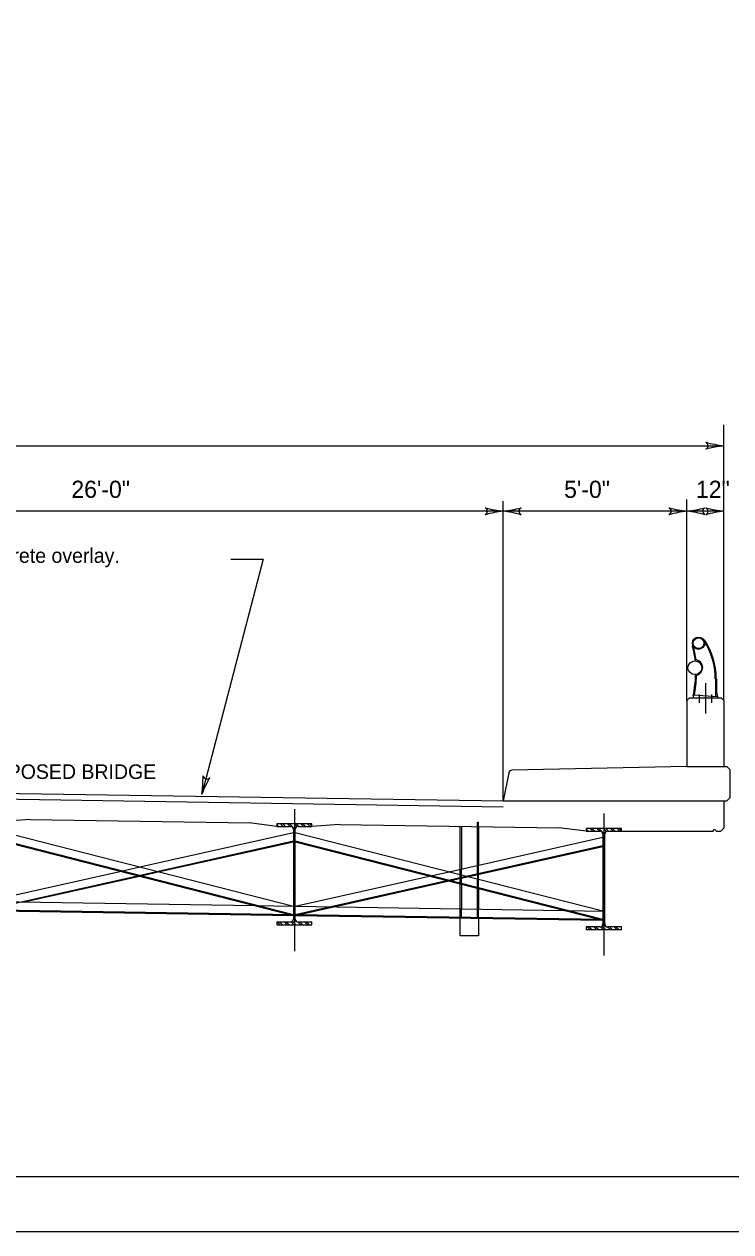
# Model space of a CAD drawing. Extents: x -706 to 14950, y -1867 to 6417.
# Drawn here: x -41.4 to 150.8, y -336.5 to -7.9 of the extents above; entities that cross this region are included whole.
import ezdxf

# ---------------------------------------------------------------- set-up
doc = ezdxf.new("R2010")
doc.units = 0
for name, color, linetype in [('Level 1', 7, 'Continuous'), ('Level 42', 7, 'Continuous'), ('Level 43', 7, 'Continuous'), ('Level 44', 7, 'Continuous'), ('Level 47', 7, 'Continuous'), ('Level 48', 7, 'Continuous')]:
    doc.layers.add(name, color=color, linetype=linetype)

msp = doc.modelspace()

# ---------------------------------------------------------------- linework, layer by layer
at = {"layer": 'Level 1'}
for p, q in [((143.95, -121.66), (143.94, -121.66)), ((93.71, -139.49), (93.72, -139.49)), ((143.71, -139.49), (143.72, -139.49)), ((83.95, -141.34), (83.94, -141.34)), ((133.95, -141.34), (133.94, -141.34)), ((143.95, -141.34), (143.94, -141.34))]:
    msp.add_line(p, q, dxfattribs=at)
for points in [[(-574.95, 323.53), (445.05, 323.53), (445.05, -336.47), (-574.95, -336.47)], [(-514.95, 308.53), (430.05, 308.53), (430.05, -321.47), (-514.95, -321.47)]]:
    msp.add_lwpolyline(points, close=True, dxfattribs=at)
for centre, start, end in [((153.23, -86.04), 255.3829, 263.1374), ((153.23, -159.12), 96.8626, 104.6171), ((93.23, -103.87), 255.3829, 263.1374), ((93.23, -176.95), 96.8626, 104.6171), ((84.43, -103.87), 276.8626, 284.6171), ((84.43, -176.95), 75.3829, 83.1374), ((143.23, -103.87), 255.3829, 263.1374), ((143.23, -176.95), 96.8626, 104.6171), ((134.43, -103.87), 276.8626, 284.6171), ((134.43, -176.95), 75.3829, 83.1374), ((153.23, -103.87), 255.3829, 263.1374), ((153.23, -176.95), 96.8626, 104.6171)]:
    msp.add_arc(centre, 36.8, start, end, dxfattribs=at)
for centre, major_axis, start_param, end_param in [((143.29, -122.58), (1.25, 0), 5.258637, 7.300638), ((83.29, -140.42), (1.25, 0), 5.265733, 7.307734), ((94.37, -140.41), (-1.25, 0), 5.265733, 7.307734), ((133.29, -140.42), (1.25, 0), 5.265733, 7.307734), ((144.37, -140.41), (-1.25, 0), 5.265733, 7.307734), ((143.29, -140.42), (1.25, 0), 5.265733, 7.307734)]:
    msp.add_ellipse(centre, major_axis=major_axis, ratio=0.873734, start_param=start_param, end_param=end_param, dxfattribs=at)
at = {"layer": 'Level 42'}
for p, q in [((143.83, -187.2), (143.83, -195.43)), ((142.16, -190.23), (142.16, -192.5)), ((145.5, -190.23), (145.5, -192.56)), ((138.83, -209.85), (148.83, -209.85)), ((-136.27, -215.71), (88.83, -219.22)), ((-136.27, -217.3), (88.83, -220.81))]:
    msp.add_line(p, q, dxfattribs=at)
at = {"layer": 'Level 43'}
for p, q in [((140.31, -177.1), (140.5, -177.05)), ((143.4, -175.45), (143.58, -175.35)), ((146.55, -185.98), (146.55, -190.85)), ((146.82, -186.01), (146.82, -189.18)), ((140.52, -190.49), (140.52, -191.31)), ((147.15, -190.89), (140.52, -190.49)), ((138.83, -191.94), (139.45, -191.31)), ((138.83, -191.94), (138.83, -209.85)), ((148.21, -191.31), (139.45, -191.31)), ((147.15, -190.89), (147.15, -191.31)), ((148.83, -191.94), (148.21, -191.31)), ((148.83, -191.94), (148.83, -209.85)), ((138.83, -209.85), (91.17, -210.88)), ((148.83, -209.85), (149.66, -209.85)), ((149.66, -209.85), (150.5, -210.68)), ((90.37, -211.55), (88.83, -219.23)), ((150.5, -210.68), (150.5, -218.39)), ((88.83, -219.23), (148.83, -219.23)), ((148.83, -219.23), (149.66, -219.23)), ((148.83, -219.23), (148.83, -226.63)), ((150.5, -218.39), (149.66, -219.23)), ((-51.86, -226.5), (31.82, -247.86)), ((-39.81, -224.3), (-47.31, -224.84)), ((-39.81, -224.3), (20.08, -225.23)), ((27.27, -226.15), (19.77, -225.23)), ((36.85, -225.42), (27.27, -225.42)), ((27.27, -225.42), (27.27, -226.15)), ((27.77, -226.15), (27.27, -225.65)), ((27.27, -226.15), (30.99, -226.15)), ((29.04, -226.15), (28.31, -225.42)), ((29.61, -226.15), (28.88, -225.42)), ((30.88, -226.15), (30.15, -225.42)), ((32.3, -227.01), (30.72, -225.42)), ((32.81, -226.24), (31.99, -225.42)), ((33.29, -226.15), (32.56, -225.42)), ((33.14, -226.15), (36.85, -226.15)), ((33.14, -226.15), (33.14, -226.15)), ((34.56, -226.15), (33.83, -225.42)), ((35.12, -226.15), (34.4, -225.42)), ((36.4, -226.15), (35.67, -225.42)), ((36.85, -226.04), (36.23, -225.42)), ((36.85, -226.15), (36.85, -225.42)), ((44.35, -225.61), (36.85, -226.15)), ((44.35, -225.61), (103.94, -226.54)), ((77.17, -237.83), (77.17, -226.13)), ((77.48, -226.13), (77.48, -237.76)), ((81.86, -226.2), (81.86, -224.98)), ((81.86, -236.78), (81.86, -226.2)), ((82.17, -226.2), (82.17, -224.9)), ((82.17, -226.2), (82.17, -236.71)), ((111.44, -227.47), (103.94, -226.54)), ((148, -227.47), (148.83, -226.63)), ((31.82, -250.19), (-51.86, -228.84)), ((31.82, -250.46), (-51.86, -229.1)), ((-10, -237.19), (31.82, -227.82)), ((31.82, -226.98), (31.82, -251.36)), ((32.3, -227.57), (31.82, -227.09)), ((32.3, -228.85), (31.82, -228.36)), ((32.3, -229.41), (31.82, -228.93)), ((32.3, -251.36), (32.3, -226.98)), ((32.3, -227.82), (115.99, -249.17)), ((74.17, -238.5), (115.99, -229.13)), ((121.02, -226.74), (111.44, -226.74)), ((111.44, -226.74), (111.44, -227.47)), ((111.94, -227.47), (111.44, -226.97)), ((111.44, -227.47), (115.15, -227.47)), ((113.21, -227.47), (112.48, -226.74)), ((113.77, -227.47), (113.05, -226.74)), ((115.05, -227.47), (114.32, -226.74)), ((116.47, -228.32), (114.88, -226.74)), ((115.99, -228.3), (115.99, -252.67)), ((116.47, -228.89), (115.99, -228.4)), ((116.47, -230.16), (115.99, -229.68)), ((116.98, -227.56), (116.16, -226.74)), ((116.47, -252.67), (116.47, -228.3)), ((117.45, -227.47), (116.72, -226.74)), ((117.3, -227.47), (121.02, -227.47)), ((117.3, -227.47), (117.3, -227.47)), ((118.72, -227.47), (118, -226.74)), ((119.29, -227.47), (118.56, -226.74)), ((120.56, -227.47), (119.83, -226.74)), ((121.02, -227.36), (120.4, -226.74)), ((121.02, -227.47), (121.02, -226.74)), ((121.02, -227.47), (145.91, -227.47)), ((146.73, -227.47), (148, -227.47)), ((31.82, -230.13), (-51.86, -248.88)), ((31.82, -230.4), (-4.62, -238.56)), ((32.3, -230.68), (31.82, -230.2)), ((32.3, -231.25), (31.82, -230.77)), ((32.3, -232.52), (31.82, -232.04)), ((32.3, -233.09), (31.82, -232.6)), ((115.99, -251.5), (32.3, -230.15)), ((115.99, -251.77), (32.3, -230.42)), ((115.99, -231.45), (32.3, -250.19)), ((115.99, -231.71), (79.55, -239.87)), ((116.47, -230.73), (115.99, -230.24)), ((116.47, -232), (115.99, -231.52)), ((116.47, -232.56), (115.99, -232.08)), ((32.3, -234.36), (31.82, -233.88)), ((32.3, -234.93), (31.82, -234.44)), ((32.3, -236.2), (31.82, -235.72)), ((32.3, -236.76), (31.82, -236.28)), ((116.47, -233.84), (115.99, -233.35)), ((116.47, -234.4), (115.99, -233.92)), ((116.47, -235.68), (115.99, -235.19)), ((116.47, -236.24), (115.99, -235.76)), ((-51.86, -246.56), (-15.43, -238.4)), ((-10.04, -239.78), (-41.42, -246.8)), ((-15.43, -238.4), (-10, -237.19)), ((-4.62, -238.56), (-10.04, -239.78)), ((32.3, -238.04), (31.82, -237.55)), ((32.3, -238.6), (31.82, -238.12)), ((32.3, -239.88), (31.82, -239.39)), ((32.3, -247.88), (68.74, -239.72)), ((68.74, -239.72), (74.16, -238.5)), ((77.17, -241.87), (77.17, -237.83)), ((77.48, -241.95), (77.48, -237.76)), ((81.86, -239.36), (81.86, -236.78)), ((81.86, -239.36), (81.86, -240.46)), ((82.17, -239.29), (82.17, -236.71)), ((82.17, -240.54), (82.17, -239.29)), ((116.47, -237.51), (115.99, -237.03)), ((116.47, -238.08), (115.99, -237.6)), ((116.47, -239.35), (115.99, -238.87)), ((116.47, -239.92), (115.99, -239.43)), ((32.3, -240.44), (31.82, -239.96)), ((32.3, -241.71), (31.82, -241.23)), ((32.3, -242.28), (31.82, -241.8)), ((32.3, -243.55), (31.82, -243.07)), ((74.12, -241.09), (42.75, -248.12)), ((79.55, -239.87), (74.12, -241.09)), ((77.17, -248.66), (77.17, -241.87)), ((77.48, -241.95), (77.48, -248.67)), ((81.86, -243.06), (81.86, -240.46)), ((81.86, -248.74), (81.86, -243.06)), ((82.17, -243.14), (82.17, -240.54)), ((82.17, -243.14), (82.17, -248.74)), ((116.47, -241.19), (115.99, -240.71)), ((116.47, -241.76), (115.99, -241.27)), ((116.47, -243.03), (115.99, -242.55)), ((116.47, -243.6), (115.99, -243.11)), ((32.3, -244.12), (31.82, -243.64)), ((32.3, -245.39), (31.82, -244.91)), ((32.3, -245.96), (31.82, -245.47)), ((116.47, -244.87), (115.99, -244.38)), ((116.47, -245.43), (115.99, -244.95)), ((116.47, -246.71), (115.99, -246.22)), ((21.27, -247.79), (-51.86, -246.64)), ((31.82, -250.2), (-51.86, -248.88)), ((31.82, -250.46), (-51.86, -249.14)), ((31.82, -247.96), (21.38, -247.79)), ((32.3, -247.23), (31.82, -246.75)), ((32.3, -247.8), (31.82, -247.31)), ((32.3, -249.07), (31.82, -248.58)), ((32.3, -249.63), (31.82, -249.15)), ((105.44, -249.11), (32.3, -247.96)), ((42.73, -248.12), (32.3, -250.46)), ((77.17, -251.16), (77.17, -248.66)), ((77.48, -251.17), (77.48, -248.67)), ((81.86, -251.24), (81.86, -248.74)), ((82.17, -251.24), (82.17, -248.74)), ((115.99, -249.27), (105.54, -249.11)), ((116.47, -247.27), (115.99, -246.79)), ((116.47, -248.54), (115.99, -248.06)), ((116.47, -249.11), (115.99, -248.63)), ((30.99, -252.19), (27.27, -252.19)), ((27.27, -252.19), (27.27, -252.92)), ((27.27, -252.92), (36.85, -252.92)), ((28.24, -252.92), (27.51, -252.19)), ((28.8, -252.92), (28.07, -252.19)), ((30.08, -252.92), (29.35, -252.19)), ((30.64, -252.92), (29.91, -252.19)), ((31.91, -252.92), (31.15, -252.16)), ((32.48, -252.92), (31.53, -251.97)), ((32.3, -250.91), (31.82, -250.42)), ((32.32, -251.49), (31.82, -250.99)), ((115.99, -251.51), (32.3, -250.2)), ((115.99, -251.77), (32.3, -250.46)), ((33.75, -252.92), (32.99, -252.16)), ((36.85, -252.19), (33.14, -252.19)), ((34.32, -252.92), (33.59, -252.19)), ((35.59, -252.92), (34.86, -252.19)), ((36.16, -252.92), (35.43, -252.19)), ((36.85, -252.35), (36.7, -252.19)), ((36.85, -252.92), (36.85, -252.12)), ((77.17, -255.9), (77.17, -251.16)), ((82.17, -251.24), (82.17, -255.9)), ((116.47, -250.38), (115.99, -249.9)), ((116.47, -250.95), (115.99, -250.47)), ((116.47, -252.22), (115.99, -251.74)), ((116.48, -252.8), (115.99, -252.3)), ((82.17, -255.9), (77.17, -255.9)), ((115.15, -253.51), (111.44, -253.51)), ((111.44, -253.51), (111.44, -254.24)), ((111.44, -254.24), (121.02, -254.24)), ((112.4, -254.24), (111.67, -253.51)), ((112.97, -254.24), (112.24, -253.51)), ((114.24, -254.24), (113.51, -253.51)), ((114.81, -254.24), (114.08, -253.51)), ((116.08, -254.24), (115.32, -253.48)), ((116.65, -254.24), (115.69, -253.28)), ((117.92, -254.24), (117.15, -253.47)), ((121.02, -253.51), (117.3, -253.51)), ((118.48, -254.24), (117.75, -253.51)), ((119.76, -254.24), (119.03, -253.51)), ((120.32, -254.24), (119.59, -253.51)), ((121.02, -253.66), (120.87, -253.51)), ((121.02, -254.24), (121.02, -253.44))]:
    msp.add_line(p, q, dxfattribs=at)
for centre, radius in [((141.99, -176.32), 1.66), ((141.99, -176.32), 1.46), ((140.98, -182.98), 1.87)]:
    msp.add_circle(centre, radius, dxfattribs=at)
for centre, radius, start, end in [((119.8, -183.42), 21.46, 6.1531, 17.1122), ((119.8, -183.42), 21.65, 6.8219, 17.1122), ((143.88, -177.11), 0.394, 28.6512, 157.265), ((127.64, -185.99), 19.16, 359.9287, 33.7121), ((127.64, -185.99), 18.9, 359.9287, 28.6512), ((140.98, -182.98), 2.13, 280.8945, 81.1945), ((119.47, -185.48), 21.65, 346.5742, 1.6594), ((119.47, -185.48), 21.92, 346.5742, 1.0208), ((151.81, -189.12), 4.99, 180.6213, 200.7537), ((91.18, -211.71), 0.833, 91.2327, 168.6901), ((30.99, -226.98), 0.833, 0, 90), ((33.14, -226.98), 0.833, 90, 180), ((115.15, -228.3), 0.833, 0, 90), ((117.3, -228.3), 0.833, 90, 180), ((146.33, -227.47), 0.417, 0, 180.0018), ((30.99, -251.36), 0.833, 270, 0), ((33.14, -251.36), 0.833, 180, 270), ((115.15, -252.67), 0.833, 270, 0), ((117.3, -252.67), 0.833, 180, 270)]:
    msp.add_arc(centre, radius, start, end, dxfattribs=at)
at = {"layer": 'Level 47'}
for p, q in [((148.83, -191.94), (148.83, -116.91)), ((-421.38, -122.58), (148.83, -122.58)), ((88.83, -219.23), (88.83, -137.69)), ((138.83, -191.94), (138.83, -137.23)), ((88.83, -140.41), (-136.27, -140.41)), ((138.83, -140.41), (88.83, -140.41)), ((148.83, -140.41), (138.83, -140.41)), ((23.55, -153.41), (6.9, -217.39)), ((14.78, -153.41), (23.55, -153.41)), ((9.02, -212.9), (9.03, -212.89))]:
    msp.add_line(p, q, dxfattribs=at)
for centre, start, end in [((-29.57, -212.44), 352.2739, 0.0284), ((41.15, -230.85), 150.7942, 158.5486)]:
    msp.add_arc(centre, 36.8, start, end, dxfattribs=at)
msp.add_ellipse((8.29, -212.03), major_axis=(-0.31, -1.21), ratio=0.873734, start_param=5.258637, end_param=7.300638, dxfattribs=at)
at = {"layer": 'Level 48'}
for p, q in [((32.06, -221.49), (32.06, -260.09)), ((116.23, -222.66), (116.23, -261.25))]:
    msp.add_line(p, q, dxfattribs=at)

# ---------------------------------------------------------------- texts
at = {"layer": 'Level 44'}
for s, height, p in [('26\'-0"', 4.68, (-28.59, -136.78)), ('5\'-0"', 4.68, (105.42, -136.78)), ('12"', 4.68, (141.28, -136.78)), ('1 1/4" Micro-silica Modified Concrete overlay.', 3.9688, (-121.71, -154.45)), ('PROPOSED BRIDGE', 3.9688, (-57.41, -213.25))]:
    msp.add_text(s, height=height, dxfattribs=at).set_placement(p)

doc.saveas('drawing.dxf')
